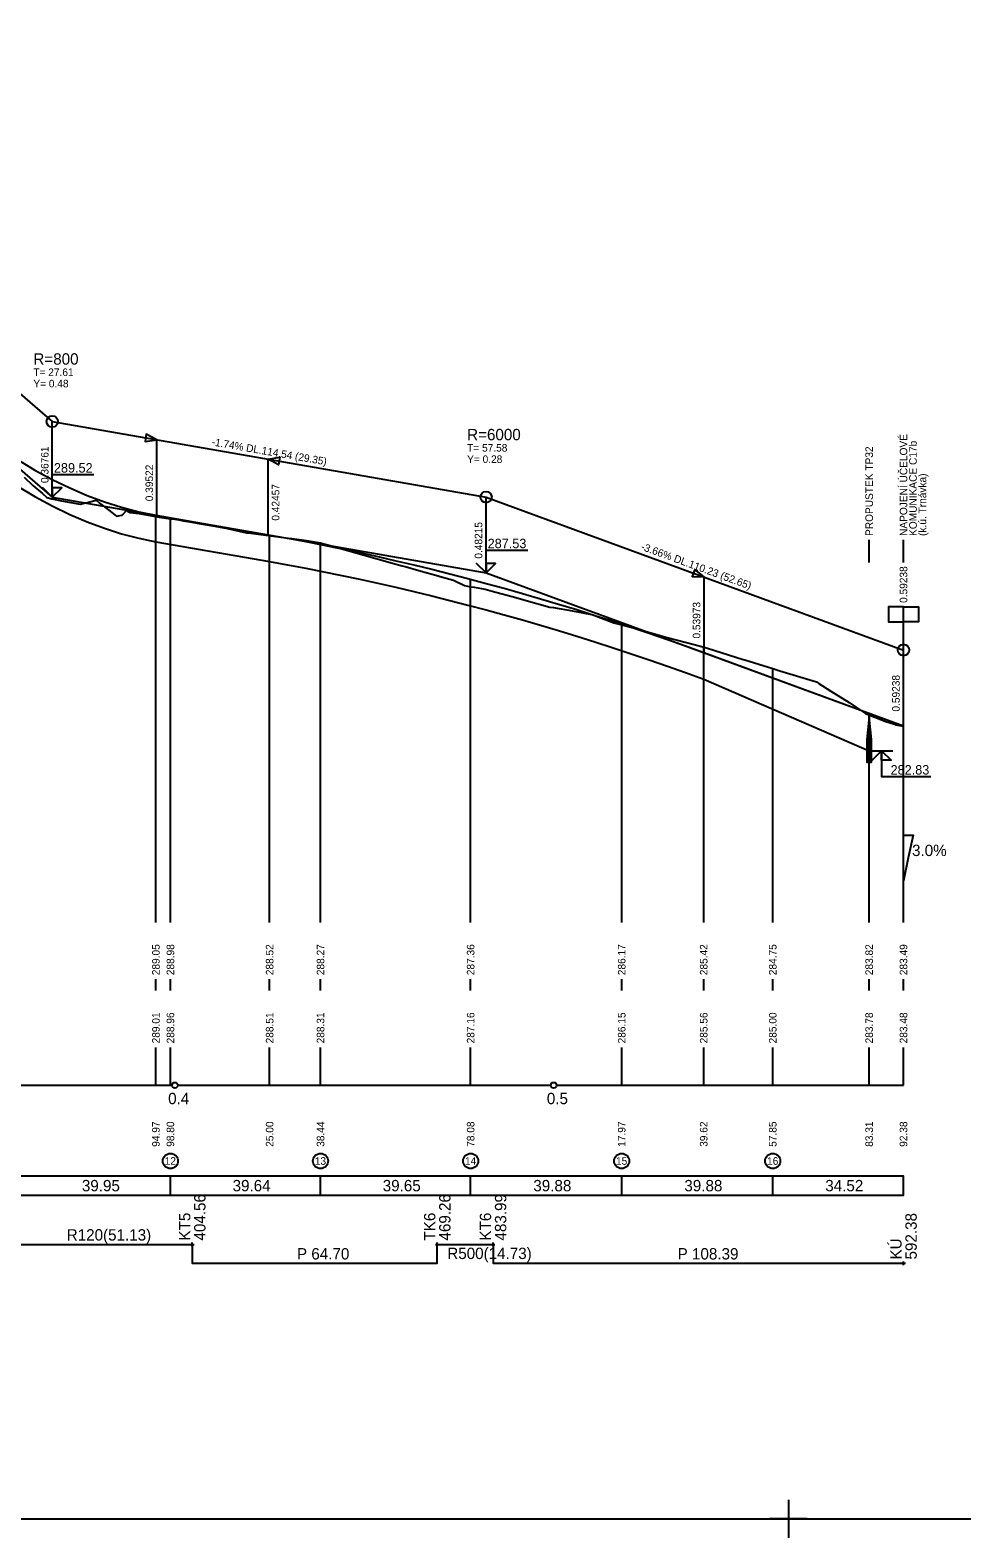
# Model space of a CAD drawing. Extents: x -4 to 847, y -64 to 540.
# Drawn here: x 431.8 to 677.8, y -64.5 to 333.5 of the extents above; entities that cross this region are included whole.
import ezdxf

# ---------------------------------------------------------------- set-up
doc = ezdxf.new("R2010")
doc.units = 0
for name, color, linetype in [('KOTA', 7, 'Continuous'), ('KRIZENI', 7, 'Continuous'), ('NOVY_STAV', 7, 'Continuous'), ('NS_OBLOUK', 7, 'Continuous'), ('POPISY_NAD_TERENEM', 7, 'Continuous'), ('PRIKOPY', 7, 'Continuous'), ('REZY_PO', 7, 'Continuous'), ('SESTAVY_REZU_PO', 7, 'Continuous'), ('SKLONOVE_POMERY', 7, 'Continuous'), ('SMEROVE_POMERY', 7, 'Continuous'), ('SMEROVE_POMERY_KOD', 7, 'Continuous'), ('SVK_STAT', 7, 'Continuous'), ('TABULKY', 7, 'Continuous'), ('ZNACKY', 7, 'Continuous')]:
    doc.layers.add(name, color=color, linetype=linetype)

msp = doc.modelspace()

# ---------------------------------------------------------------- linework, layer by layer
for p, q in [((631.97, -54.48), (631.97, -64.48)), ((631.97, -54.48), (631.97, -64.48)), ((631.97, -54.48), (631.97, -64.48)), ((631.97, -54.48), (631.97, -64.48)), ((631.97, -54.48), (631.97, -64.48)), ((631.97, -54.48), (631.97, -64.48)), ((631.97, -54.48), (631.97, -64.48)), ((631.97, -54.48), (631.97, -64.48)), ((631.97, -54.48), (631.97, -64.48)), ((631.97, -54.48), (631.97, -64.48)), ((631.97, -54.48), (631.97, -64.48)), ((631.97, -54.48), (631.97, -64.48)), ((631.97, -54.48), (631.97, -64.48)), ((631.97, -54.48), (631.97, -64.48)), ((631.97, -54.48), (631.97, -64.48)), ((631.97, -54.48), (631.97, -64.48)), ((631.97, -54.48), (631.97, -64.48)), ((631.97, -54.48), (631.97, -64.48)), ((631.97, -54.48), (631.97, -64.48)), ((631.97, -54.48), (631.97, -64.48)), ((631.97, -54.48), (631.97, -64.48)), ((631.97, -54.48), (631.97, -64.48)), ((631.97, -54.48), (631.97, -64.48)), ((631.97, -54.48), (631.97, -64.48)), ((636.97, -59.48), (626.97, -59.48)), ((636.97, -59.48), (626.97, -59.48)), ((636.97, -59.48), (626.97, -59.48)), ((636.97, -59.48), (626.97, -59.48)), ((636.97, -59.48), (626.97, -59.48)), ((636.97, -59.48), (626.97, -59.48)), ((636.97, -59.48), (626.97, -59.48)), ((636.97, -59.48), (626.97, -59.48)), ((636.97, -59.48), (626.97, -59.48)), ((636.97, -59.48), (626.97, -59.48)), ((636.97, -59.48), (626.97, -59.48)), ((636.97, -59.48), (626.97, -59.48)), ((636.97, -59.48), (626.97, -59.48)), ((636.97, -59.48), (626.97, -59.48)), ((636.97, -59.48), (626.97, -59.48)), ((636.97, -59.48), (626.97, -59.48)), ((636.97, -59.48), (626.97, -59.48)), ((636.97, -59.48), (626.97, -59.48)), ((636.97, -59.48), (626.97, -59.48)), ((636.97, -59.48), (626.97, -59.48)), ((636.97, -59.48), (626.97, -59.48)), ((636.97, -59.48), (626.97, -59.48)), ((636.97, -59.48), (626.97, -59.48)), ((636.97, -59.48), (626.97, -59.48))]:
    msp.add_line(p, q)
msp.add_lwpolyline([(841.97, 534.52), (1.47, 534.52), (1.47, -59.48), (841.97, -59.48)], close=True)
at = {"layer": 'KOTA'}
for points in [[(437.61, 210.22), (435.11, 212.72), (437.61, 210.22), (437.61, 216.22), (448.61, 216.22)], [(437.61, 210.22), (440.11, 212.72), (437.61, 212.72), (437.61, 210.22)], [(437.61, 210.22), (440.11, 212.72), (437.61, 212.72)], [(437.61, 210.22), (437.61, 210.22)], [(552.15, 190.26), (549.65, 192.76), (552.15, 190.26), (552.15, 196.26), (563.15, 196.26)], [(552.15, 190.26), (554.65, 192.76), (552.15, 192.76), (552.15, 190.26)], [(552.15, 190.26), (554.65, 192.76), (552.15, 192.76)], [(552.15, 190.26), (552.15, 190.26)], [(653.31, 143.27), (656.6, 143.27), (659.6, 143.27)], [(656.6, 143.27), (654.1, 140.77), (656.6, 143.27), (656.6, 136.51), (669.56, 136.51)], [(656.6, 143.27), (659.1, 140.77), (656.6, 140.77), (656.6, 143.27)], [(656.6, 143.27), (659.1, 140.77), (656.6, 140.77)]]:
    msp.add_lwpolyline(points, dxfattribs=at)
at = {"layer": 'KRIZENI'}
for points in [[(653.91, 146.27), (653.31, 152.27), (652.71, 146.27), (653.31, 140.27)], [(653.61, 146.27), (653.31, 149.27), (653.01, 146.27), (653.31, 143.27)]]:
    msp.add_lwpolyline(points, close=True, dxfattribs=at)
msp.add_lwpolyline([(652.71, 146.27), (652.71, 140.27), (653.91, 140.27), (653.91, 146.27)], dxfattribs=at)
at = {"layer": 'NOVY_STAV'}
for points in [[(70, 340.7), (158.48, 384.52), (323.51, 308.85), (437.61, 210.22), (552.15, 190.26), (662.38, 149.89)], [(323.51, 328.85), (437.61, 230.22)], [(437.61, 210.22), (437.61, 230.22)], [(437.61, 230.22), (552.15, 210.26)], [(428.42, 220.15), (433.02, 217.4), (437.61, 214.92), (442.21, 212.69), (446.81, 210.72), (451.38, 209.02), (455.91, 207.58), (460.44, 206.39), (464.97, 205.47), (495, 200.23), (499.76, 199.38), (504.52, 198.49), (509.28, 197.56), (514.04, 196.6), (518.8, 195.59), (523.56, 194.55), (528.32, 193.47), (533.08, 192.35), (537.84, 191.19), (542.6, 190), (547.36, 188.76), (552.15, 187.49), (556.94, 186.18), (561.73, 184.83), (566.52, 183.44), (571.31, 182.01), (576.1, 180.55), (580.88, 179.04), (585.67, 177.5), (590.46, 175.92), (595.25, 174.3), (600.04, 172.64), (604.83, 170.95), (609.62, 169.21), (662.38, 149.89)], [(552.15, 190.26), (552.15, 210.26)], [(552.15, 210.26), (662.38, 169.89)], [(662.38, 149.89), (662.38, 169.89)]]:
    msp.add_lwpolyline(points, dxfattribs=at)
for centre in [(437.61, 230.22), (552.15, 210.26), (662.38, 169.89)]:
    msp.add_circle(centre, 1.5, dxfattribs=at)
at = {"layer": 'NS_OBLOUK'}
for points in [[(465.22, 225.41), (462.44, 226.91), (462.09, 224.94), (465.22, 225.41)], [(465.22, 205.41), (465.22, 225.41)], [(494.57, 220.29), (497.7, 220.76), (497.35, 218.79), (494.57, 220.29)], [(494.57, 200.29), (494.57, 220.29)], [(609.73, 189.17), (607.26, 191.14), (606.57, 189.26), (609.73, 189.17)], [(609.73, 169.17), (609.73, 189.17)]]:
    msp.add_lwpolyline(points, dxfattribs=at)
for points in [[(465.22, 225.41), (462.44, 226.91), (462.09, 224.94)], [(494.57, 220.29), (497.7, 220.76), (497.35, 218.79)], [(609.73, 189.17), (607.26, 191.14), (606.57, 189.26)]]:
    msp.add_lwpolyline(points, close=True, dxfattribs=at)
at = {"layer": 'POPISY_NAD_TERENEM'}
for points in [[(653.31, 193), (653.31, 199)], [(662.38, 193), (662.38, 199)]]:
    msp.add_lwpolyline(points, dxfattribs=at)
at = {"layer": 'PRIKOPY'}
msp.add_lwpolyline([(428.42, 213.15), (433.02, 210.4), (437.61, 207.92), (442.21, 205.69), (446.81, 203.72), (451.38, 202.02), (455.91, 200.58), (460.44, 199.39), (464.97, 198.47), (495, 193.23), (499.76, 192.38), (504.52, 191.49), (509.28, 190.56), (514.04, 189.6), (518.8, 188.59), (523.56, 187.55), (528.32, 186.47), (533.08, 185.35), (537.84, 184.19), (542.6, 183), (547.36, 181.76), (552.15, 180.49), (556.94, 179.18), (561.73, 177.83), (566.52, 176.44), (571.31, 175.01), (576.1, 173.55), (580.88, 172.04), (585.67, 170.5), (590.46, 168.92), (595.25, 167.3), (600.04, 165.64), (604.83, 163.95), (609.62, 162.21), (653.31, 143.27)], dxfattribs=at)
at = {"layer": 'REZY_PO'}
msp.add_lwpolyline([(430.17, 215.53), (432.5, 213.36), (435, 211.18), (436.21, 210.19), (437.5, 209.84), (440, 209.26), (442.5, 208.79), (445, 208.43), (445.06, 208.42), (447.5, 208.97), (449.17, 209.42), (450, 208.76), (452.5, 206.8), (454.56, 205.26), (455, 205.32), (456.01, 205.51), (456.02, 205.52), (457.17, 206.71), (457.5, 206.55), (458.14, 206.23), (459.66, 206.05), (460, 205.99), (462.93, 205.47), (465.87, 205), (468.8, 204.56), (469.4, 204.48), (470, 204.39), (471.02, 204.26), (472.24, 204.02), (474.48, 203.63), (476.3, 203.32), (480, 202.65), (483.9, 201.94), (488.89, 200.86), (490, 200.71), (500, 199.42), (500.84, 199.31), (504.76, 198.8), (508.44, 198.14), (508.72, 198.09), (510, 197.73), (520, 194.89), (527.42, 192.79), (530, 192.14), (530.83, 191.93), (534.36, 190.89), (539.46, 189.48), (539.73, 189.41), (540, 189.33), (543.53, 188.36), (544.04, 188.1), (546.43, 186.9), (548.08, 186.6), (549.04, 186.44), (550, 186.27), (551.87, 185.96), (551.87, 185.96), (553.74, 185.44), (560, 183.72), (562.73, 182.96), (569.02, 181.24), (570, 181.08), (574.96, 180.23), (580, 179.26), (580.14, 179.23), (585.89, 177.08), (587.97, 176.52), (590, 175.98), (596.67, 174.2), (599.63, 173.31), (600, 173.21), (607.09, 171.36), (610, 170.52), (610.58, 170.36), (620, 167.42), (620.48, 167.27), (627.85, 164.97), (630, 164.3), (630.3, 164.21), (630.63, 164.11), (639.37, 161.49), (640, 161.09), (643.18, 159.06), (648.01, 156.02), (650, 154.69), (652.35, 153.12), (657.71, 151.06), (660, 150.27), (660.27, 150.17), (662.38, 149.77)], dxfattribs=at)
at = {"layer": 'SESTAVY_REZU_PO'}
for points in [[(370.75, 55), (469.25, 55)], [(470.75, 55), (569.25, 55)], [(570.75, 55), (662.38, 55)], [(468.8, 26), (468.8, 31)], [(508.44, 26), (508.44, 31)], [(548.08, 26), (548.08, 31)], [(587.97, 26), (587.97, 31)], [(627.85, 26), (627.85, 31)]]:
    msp.add_lwpolyline(points, dxfattribs=at)
for centre in [(470, 55), (570, 55)]:
    msp.add_circle(centre, 0.75, dxfattribs=at)
at = {"layer": 'SKLONOVE_POMERY'}
msp.add_lwpolyline([(662.38, 109), (662.38, 121), (664.9, 121), (663.64, 115), (662.38, 109), (662.38, 109)], dxfattribs=at)
at = {"layer": 'SMEROVE_POMERY'}
msp.add_lwpolyline([(423.42, 13), (474.56, 13), (474.56, 8), (539.26, 8), (539.26, 13), (553.99, 13), (553.99, 8), (662.38, 8)], dxfattribs=at)
at = {"layer": 'SMEROVE_POMERY_KOD'}
for points in [[(474.06, 13), (475.06, 13)], [(474.56, 12.5), (474.56, 13.5)], [(538.76, 13), (539.76, 13)], [(539.26, 12.5), (539.26, 13.5)], [(553.49, 13), (554.49, 13)], [(553.99, 12.5), (553.99, 13.5)], [(661.88, 8), (662.88, 8)], [(662.38, 7.5), (662.38, 8.5)]]:
    msp.add_lwpolyline(points, dxfattribs=at)
at = {"layer": 'SVK_STAT'}
for points in [[(464.97, 98), (464.97, 205.47)], [(468.8, 98), (468.8, 204.8)], [(495, 98), (495, 200.23)], [(508.44, 98), (508.44, 198.14)], [(548.08, 98), (548.08, 188.57)], [(587.97, 98), (587.97, 176.74)], [(609.62, 98), (609.62, 170.63)], [(627.85, 98), (627.85, 164.97)], [(653.31, 98), (653.31, 153.21)], [(662.38, 98), (662.38, 149.89)], [(464.97, 80), (464.97, 83)], [(468.8, 80), (468.8, 83)], [(495, 80), (495, 83)], [(508.44, 80), (508.44, 83)], [(548.08, 80), (548.08, 83)], [(587.97, 80), (587.97, 83)], [(609.62, 80), (609.62, 83)], [(627.85, 80), (627.85, 83)], [(653.31, 80), (653.31, 83)], [(662.38, 80), (662.38, 83)], [(464.97, 55), (464.97, 65)], [(468.8, 55), (468.8, 65)], [(495, 55), (495, 65)], [(508.44, 55), (508.44, 65)], [(548.08, 55), (548.08, 65)], [(587.97, 55), (587.97, 65)], [(609.62, 55), (609.62, 65)], [(627.85, 55), (627.85, 65)], [(653.31, 55), (653.31, 65)], [(662.38, 55), (662.38, 65)]]:
    msp.add_lwpolyline(points, dxfattribs=at)
for centre in [(468.8, 35), (508.44, 35), (548.08, 35), (587.97, 35), (627.85, 35)]:
    msp.add_circle(centre, 2, dxfattribs=at)
at = {"layer": 'TABULKY'}
msp.add_lwpolyline([(70, 26), (662.38, 26), (662.38, 31), (70, 31), (70, 26)], dxfattribs=at)
at = {"layer": 'ZNACKY'}
for points in [[(662.38, 149.89), (662.38, 181.32), (658.38, 181.32), (658.38, 177.32), (662.38, 177.32)], [(662.38, 181.32), (666.38, 181.32), (666.38, 177.32), (662.38, 177.32)]]:
    msp.add_lwpolyline(points, dxfattribs=at)

# ---------------------------------------------------------------- texts
at = {"layer": 'KOTA'}
for s, p in [('289.52', (438.03, 216.72)), ('287.53', (552.57, 196.76)), ('282.83', (658.97, 137.01))]:
    msp.add_text(s, height=2.5, dxfattribs=at).set_placement(p)
at = {"layer": 'NOVY_STAV'}
for s, rotation, p in [(' 0.36761', 90, (436.61, 213.22)), ('-1.74% DL.114.54 (29.35)', 350.1149, (479.59, 223.92)), (' 0.48215', 90, (551.15, 193.26)), ('-3.66% DL.110.23 (52.65)', 339.8877, (592.87, 196.41)), (' 0.59238', 90, (661.38, 152.89))]:
    msp.add_text(s, height=2, rotation=rotation, dxfattribs=at).set_placement(p)
at = {"layer": 'NS_OBLOUK'}
for s, height, p in [('R=800', 3, (432.61, 245.22)), ('T= 27.61', 2, (432.61, 242.22)), ('Y= 0.48', 2, (432.61, 239.22)), ('R=6000', 3, (547.15, 225.26)), ('T= 57.58', 2, (547.15, 222.26)), ('Y= 0.28', 2, (547.15, 219.26))]:
    msp.add_text(s, height=height, dxfattribs=at).set_placement(p)
for s, p in [(' 0.39522', (464.22, 208.41)), (' 0.42457', (497.57, 203.29)), (' 0.53973', (608.73, 172.17))]:
    msp.add_text(s, height=2, rotation=90, dxfattribs=at).set_placement(p)
at = {"layer": 'POPISY_NAD_TERENEM'}
for s, p in [('PROPUSTEK TP32', (654.31, 200)), ('NAPOJENÍ ÚČELOVÉ', (663.38, 200)), ('KOMUNIKACE C17b', (665.88, 200)), ('(k.ú. Trnávka)', (668.38, 200))]:
    msp.add_text(s, height=2, rotation=90, dxfattribs=at).set_placement(p)
at = {"layer": 'SESTAVY_REZU_PO'}
for s, p in [('0.4', (468.2, 50)), ('0.5', (568.2, 50)), ('39.95', (445.42, 27)), ('39.64', (485.22, 27)), ('39.65', (524.86, 27)), ('39.88', (564.63, 27)), ('39.88', (604.51, 27)), ('34.52', (641.72, 27))]:
    msp.add_text(s, height=3, dxfattribs=at).set_placement(p)
at = {"layer": 'SKLONOVE_POMERY'}
msp.add_text('3.0%', height=3, dxfattribs=at).set_placement((664.64, 115.5))
at = {"layer": 'SMEROVE_POMERY'}
for s, p in [('R120(51.13)', (441.42, 14)), ('P 64.70', (502.22, 9)), ('R500(14.73)', (541.91, 9.12)), ('P 108.39', (602.74, 9))]:
    msp.add_text(s, height=3, dxfattribs=at).set_placement(p)
at = {"layer": 'SMEROVE_POMERY_KOD'}
for s, p in [('404.56', (478.06, 14)), ('469.26', (542.76, 14)), ('483.99', (557.49, 14)), ('KT5', (474.06, 14)), ('TK6', (538.76, 14)), ('KT6', (553.49, 14)), ('592.38', (665.88, 9)), ('KÚ', (661.88, 9))]:
    msp.add_text(s, height=3, rotation=90, dxfattribs=at).set_placement(p)
at = {"layer": 'SVK_STAT'}
for s, p in [(' 289.05', (465.97, 83.3)), (' 288.98', (469.8, 83.3)), (' 288.52', (496, 83.3)), (' 288.27', (509.44, 83.3)), (' 287.36', (549.08, 83.3)), (' 286.17', (588.97, 83.3)), (' 285.42', (610.62, 83.3)), (' 284.75', (628.85, 83.3)), (' 283.82', (654.31, 83.3)), (' 283.49', (663.38, 83.3)), (' 289.01', (465.97, 65.3)), (' 288.96', (469.8, 65.3)), (' 288.51', (496, 65.3)), (' 288.31', (509.44, 65.3)), (' 287.16', (549.08, 65.3)), (' 286.15', (588.97, 65.3)), (' 285.56', (610.62, 65.3)), (' 285.00', (628.85, 65.3)), (' 283.78', (654.31, 65.3)), (' 283.48', (663.38, 65.3)), (' 94.97', (465.97, 38)), (' 98.80', (469.8, 38)), (' 25.00', (496, 38)), (' 38.44', (509.44, 38)), (' 78.08', (549.08, 38)), (' 17.97', (588.97, 38)), (' 39.62', (610.62, 38)), (' 57.85', (628.85, 38)), (' 83.31', (654.31, 38)), (' 92.38', (663.38, 38))]:
    msp.add_text(s, height=2, rotation=90, dxfattribs=at).set_placement(p)
for s, p in [('12', (467.29, 34)), ('13', (506.93, 34)), ('14', (546.58, 34)), ('15', (586.46, 34)), ('16', (626.35, 34))]:
    msp.add_text(s, height=2, dxfattribs=at).set_placement(p)
at = {"layer": 'ZNACKY'}
msp.add_text('0.59238', height=2, rotation=90, dxfattribs=at).set_placement((663.38, 182.32))

doc.saveas('drawing.dxf')
